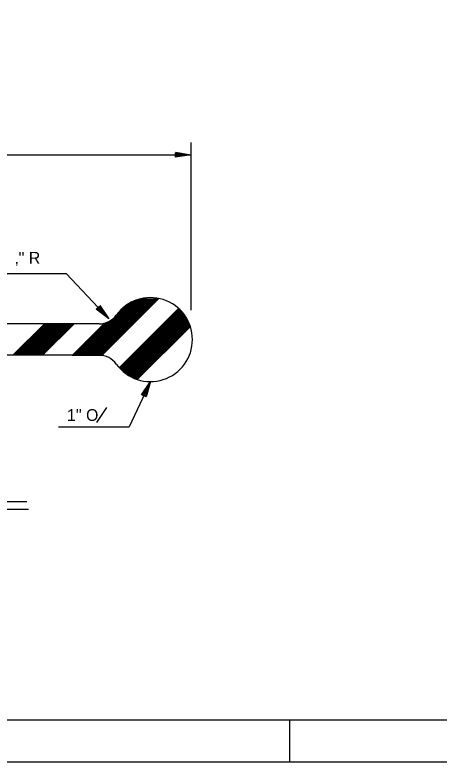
# Model space of a CAD drawing. Extents: x 44743.44 to 44747.1, y 44738.46 to 44741.29.
# Drawn here: x 44744.597 to 44745.018, y 44738.458 to 44739.199 of the extents above; entities that cross this region are included whole.
import ezdxf

# ---------------------------------------------------------------- set-up
doc = ezdxf.new("R2010")
doc.units = 0
for name, color, linetype in [('Level 1', 7, 'Continuous'), ('Level 10', 7, 'Continuous'), ('Level 2', 7, 'Continuous'), ('Level 7', 7, 'Continuous'), ('Level 8', 7, 'Continuous'), ('Level 9', 7, 'Continuous'), ('S-ANNO-TEXT', 7, 'Continuous')]:
    doc.layers.add(name, color=color, linetype=linetype)

msp = doc.modelspace()

# ---------------------------------------------------------------- linework, layer by layer
at = {"layer": 'Level 1'}
for p, q in [((44744.77199, 44738.90593), (44744.77199, 44739.0724)), ((44744.02249, 44739.06029), (44744.77199, 44739.06029)), ((44744.76766, 44739.06029), (44744.76766, 44739.06029)), ((44744.77199, 44739.06029), (44744.77199, 44739.06029)), ((44744.68736, 44738.90061), (44744.68736, 44738.90061)), ((44744.69033, 44738.89745), (44744.69033, 44738.89745)), ((44744.73162, 44738.83523), (44744.73162, 44738.83523)), ((44744.72976, 44738.83132), (44744.72976, 44738.83132))]:
    msp.add_line(p, q, dxfattribs=at)
msp.add_lwpolyline([(44743.43805, 44741.29183), (44747.10474, 44741.29183), (44747.10474, 44738.45783), (44743.43805, 44738.45783)], close=True, dxfattribs=at)
for points in [[(44744.75641, 44739.06287), (44744.77199, 44739.06029), (44744.75641, 44739.0577), (44744.75641, 44739.06212), (44744.76766, 44739.06029), (44744.75708, 44739.05854), (44744.75708, 44739.06137), (44744.76349, 44739.06029), (44744.75774, 44739.05937), (44744.75774, 44739.06054), (44744.75916, 44739.06029)], [(44744.75911, 44738.90712), (44744.75995, 44738.90712)], [(44744.62573, 44738.8922), (44744.65531, 44738.8922)], [(44744.76831, 44738.85763), (44744.76837, 44738.85763)]]:
    msp.add_lwpolyline(points, dxfattribs=at)
at = {"layer": 'Level 10'}
for p, q in [((44744.68086, 44738.89253), (44744.47322, 44738.89253)), ((44744.68086, 44738.86128), (44744.47322, 44738.86128)), ((44744.18607, 44738.71631), (44744.60885, 44738.71631)), ((44744.18494, 44738.7086), (44744.61054, 44738.7086)), ((44744.86974, 44738.45783), (44744.86974, 44738.49983))]:
    msp.add_line(p, q, dxfattribs=at)
for centre, radius, start, end in [((44744.73162, 44738.8769), 0.04167, 215.68525, 144.31912), ((44744.68085, 44738.91336), 0.02083, 270, 324.31466), ((44744.68085, 44738.84044), 0.02083, 35.68534, 90)]:
    msp.add_arc(centre, radius, start, end, dxfattribs=at)
at = {"layer": 'Level 2'}
for p, q in [((44744.58524, 44738.94247), (44744.648, 44738.94247)), ((44744.69033, 44738.89745), (44744.648, 44738.94247)), ((44744.73162, 44738.83523), (44744.71037, 44738.79038)), ((44744.64039, 44738.79038), (44744.71037, 44738.79038))]:
    msp.add_line(p, q, dxfattribs=at)
for points in [[(44744.68154, 44738.91058), (44744.69033, 44738.89745), (44744.67777, 44738.90704), (44744.68099, 44738.91007), (44744.68736, 44738.90061), (44744.67884, 44738.90712), (44744.6809, 44738.90907), (44744.6845, 44738.90365), (44744.6799, 44738.9072), (44744.68074, 44738.90801), (44744.68154, 44738.90681)], [(44744.72261, 44738.82226), (44744.73162, 44738.83523), (44744.72729, 44738.82005), (44744.72329, 44738.82193), (44744.72976, 44738.83132), (44744.72682, 44738.82101), (44744.72425, 44738.82221), (44744.72798, 44738.82756), (44744.72635, 44738.82196), (44744.7253, 44738.82246), (44744.72613, 44738.82364)]]:
    msp.add_lwpolyline(points, dxfattribs=at)
at = {"layer": 'Level 7'}
msp.add_line((44744.67844, 44738.79478), (44744.6882, 44738.80954), dxfattribs=at)
at = {"layer": 'Level 8'}
for points in [[(44744.68345, 44738.86111), (44744.74004, 44738.9177)], [(44744.71705, 44738.91618), (44744.73826, 44738.91618)], [(44744.72182, 44738.91748), (44744.73957, 44738.91748)], [(44744.7041, 44738.90837), (44744.7305, 44738.90837)], [(44744.70584, 44738.90967), (44744.7318, 44738.90967)], [(44744.70759, 44738.91097), (44744.73309, 44738.91097)], [(44744.70957, 44738.91228), (44744.73439, 44738.91228)], [(44744.71156, 44738.91358), (44744.73568, 44738.91358)], [(44744.71409, 44738.91488), (44744.73697, 44738.91488)], [(44744.69848, 44738.90186), (44744.72404, 44738.90186)], [(44744.69942, 44738.90316), (44744.72533, 44738.90316)], [(44744.70036, 44738.90446), (44744.72662, 44738.90446)], [(44744.70073, 44738.84893), (44744.75959, 44738.90779)], [(44744.70154, 44738.90577), (44744.72791, 44738.90577)], [(44744.7027, 44738.90707), (44744.72921, 44738.90707)], [(44744.75387, 44738.90191), (44744.76461, 44738.90191)], [(44744.75518, 44738.90321), (44744.76373, 44738.90321)], [(44744.75649, 44738.90452), (44744.76285, 44738.90452)], [(44744.75781, 44738.90582), (44744.76142, 44738.90582)], [(44744.68858, 44738.89405), (44744.71626, 44738.89405)], [(44744.69134, 44738.89535), (44744.71756, 44738.89535)], [(44744.69333, 44738.89665), (44744.71886, 44738.89665)], [(44744.6948, 44738.89795), (44744.72015, 44738.89795)], [(44744.69615, 44738.89926), (44744.72144, 44738.89926)], [(44744.69736, 44738.90056), (44744.72273, 44738.90056)], [(44744.74601, 44738.8941), (44744.76956, 44738.8941)], [(44744.74732, 44738.8954), (44744.76893, 44738.8954)], [(44744.74863, 44738.8967), (44744.76831, 44738.8967)], [(44744.74994, 44738.89801), (44744.76761, 44738.89801)], [(44744.75125, 44738.89931), (44744.76684, 44738.89931)], [(44744.75256, 44738.90061), (44744.76573, 44738.90061)], [(44744.59522, 44738.86128), (44744.62647, 44738.89253)], [(44744.62059, 44738.887), (44744.65015, 44738.887)], [(44744.62188, 44738.8883), (44744.65144, 44738.8883)], [(44744.62316, 44738.8896), (44744.65272, 44738.8896)], [(44744.62445, 44738.8909), (44744.65401, 44738.8909)], [(44744.62468, 44738.86128), (44744.65593, 44738.89253)], [(44744.65415, 44738.86128), (44744.68606, 44738.89318)], [(44744.67874, 44738.88623), (44744.7085, 44738.88623)], [(44744.68005, 44738.88754), (44744.7098, 44738.88754)], [(44744.68135, 44738.88884), (44744.71109, 44738.88884)], [(44744.68265, 44738.89014), (44744.71239, 44738.89014)], [(44744.68395, 44738.89144), (44744.71368, 44738.89144)], [(44744.68525, 44738.89275), (44744.71497, 44738.89275)], [(44744.71859, 44738.83733), (44744.7712, 44738.88992)], [(44744.73815, 44738.88629), (44744.76704, 44738.88629)], [(44744.73946, 44738.88759), (44744.76833, 44738.88759)], [(44744.74077, 44738.88889), (44744.76961, 44738.88889)], [(44744.74208, 44738.89019), (44744.77051, 44738.89019)], [(44744.74339, 44738.8915), (44744.77036, 44738.8915)], [(44744.7447, 44738.8928), (44744.77019, 44738.8928)], [(44744.61286, 44738.87918), (44744.64242, 44738.87918)], [(44744.61415, 44738.88048), (44744.64371, 44738.88048)], [(44744.61544, 44738.88179), (44744.64499, 44738.88179)], [(44744.61672, 44738.88309), (44744.64629, 44738.88309)], [(44744.61801, 44738.88439), (44744.64758, 44738.88439)], [(44744.61931, 44738.88569), (44744.64886, 44738.88569)], [(44744.67093, 44738.87842), (44744.70073, 44738.87842)], [(44744.67223, 44738.87972), (44744.70204, 44738.87972)], [(44744.67354, 44738.88103), (44744.70333, 44738.88103)], [(44744.67484, 44738.88233), (44744.70462, 44738.88233)], [(44744.67614, 44738.88363), (44744.70591, 44738.88363)], [(44744.67744, 44738.88493), (44744.70721, 44738.88493)], [(44744.73031, 44738.87847), (44744.7593, 44738.87847)], [(44744.73161, 44738.87978), (44744.76059, 44738.87978)], [(44744.73292, 44738.88108), (44744.76188, 44738.88108)], [(44744.73423, 44738.88238), (44744.76316, 44738.88238)], [(44744.73555, 44738.88368), (44744.76445, 44738.88368)], [(44744.73684, 44738.88498), (44744.76574, 44738.88498)], [(44744.60514, 44738.87137), (44744.63469, 44738.87137)], [(44744.60642, 44738.87267), (44744.63598, 44738.87267)], [(44744.60771, 44738.87397), (44744.63726, 44738.87397)], [(44744.609, 44738.87528), (44744.63856, 44738.87528)], [(44744.61029, 44738.87658), (44744.63985, 44738.87658)], [(44744.61158, 44738.87788), (44744.64113, 44738.87788)], [(44744.66442, 44738.87191), (44744.69427, 44738.87191)], [(44744.66572, 44738.87321), (44744.69557, 44738.87321)], [(44744.66702, 44738.87452), (44744.69686, 44738.87452)], [(44744.66833, 44738.87582), (44744.69815, 44738.87582)], [(44744.66963, 44738.87712), (44744.69944, 44738.87712)], [(44744.72375, 44738.87196), (44744.75285, 44738.87196)], [(44744.72507, 44738.87327), (44744.75414, 44738.87327)], [(44744.72637, 44738.87457), (44744.75543, 44738.87457)], [(44744.72768, 44738.87587), (44744.75672, 44738.87587)], [(44744.72899, 44738.87717), (44744.758, 44738.87717)], [(44744.5987, 44738.86486), (44744.62825, 44738.86486)], [(44744.59998, 44738.86616), (44744.62954, 44738.86616)], [(44744.60127, 44738.86746), (44744.63083, 44738.86746)], [(44744.60257, 44738.86877), (44744.63212, 44738.86877)], [(44744.60385, 44738.87007), (44744.6334, 44738.87007)], [(44744.65661, 44738.8641), (44744.68651, 44738.8641)], [(44744.65791, 44738.8654), (44744.68781, 44738.8654)], [(44744.65921, 44738.8667), (44744.6891, 44738.8667)], [(44744.66051, 44738.86801), (44744.69039, 44738.86801)], [(44744.66182, 44738.86931), (44744.69169, 44738.86931)], [(44744.66312, 44738.87061), (44744.69298, 44738.87061)], [(44744.71589, 44738.86415), (44744.74511, 44738.86415)], [(44744.7172, 44738.86545), (44744.7464, 44738.86545)], [(44744.71851, 44738.86676), (44744.74769, 44738.86676)], [(44744.71983, 44738.86806), (44744.74898, 44738.86806)], [(44744.72113, 44738.86936), (44744.75027, 44738.86936)], [(44744.72244, 44738.87066), (44744.75156, 44738.87066)], [(44744.59612, 44738.86226), (44744.62567, 44738.86226)], [(44744.59741, 44738.86356), (44744.62696, 44738.86356)], [(44744.654, 44738.8615), (44744.68392, 44738.8615)], [(44744.65531, 44738.8628), (44744.68522, 44738.8628)], [(44744.70804, 44738.85634), (44744.73738, 44738.85634)], [(44744.70934, 44738.85764), (44744.73867, 44738.85764)], [(44744.71065, 44738.85894), (44744.73995, 44738.85894)], [(44744.71196, 44738.86025), (44744.74124, 44738.86025)], [(44744.71327, 44738.86155), (44744.74254, 44738.86155)], [(44744.71459, 44738.86285), (44744.74383, 44738.86285)], [(44744.70148, 44738.84983), (44744.73094, 44738.84983)], [(44744.7028, 44738.85113), (44744.73223, 44738.85113)], [(44744.7041, 44738.85243), (44744.73351, 44738.85243)], [(44744.70541, 44738.85373), (44744.73481, 44738.85373)], [(44744.70672, 44738.85504), (44744.73609, 44738.85504)], [(44744.70133, 44738.84853), (44744.72965, 44738.84853)], [(44744.70285, 44738.84722), (44744.72836, 44738.84722)], [(44744.70418, 44738.84592), (44744.72707, 44738.84592)], [(44744.70548, 44738.84462), (44744.72579, 44738.84462)], [(44744.70717, 44738.84332), (44744.72449, 44738.84332)], [(44744.7089, 44738.84202), (44744.7232, 44738.84202)], [(44744.71164, 44738.84071), (44744.72191, 44738.84071)], [(44744.71439, 44738.83941), (44744.72063, 44738.83941)], [(44744.71699, 44738.83811), (44744.71934, 44738.83811)]]:
    msp.add_lwpolyline(points, dxfattribs=at)
at = {"layer": 'Level 9'}
msp.add_line((44743.56305, 44738.49983), (44746.83374, 44738.49983), dxfattribs=at)

# ---------------------------------------------------------------- texts
at = {"layer": 'S-ANNO-TEXT'}
for s, p in [("‚'' R", (44744.59725, 44738.95223)), ("1'' O", (44744.64881, 44738.79623))]:
    msp.add_text(s, height=0.011667, dxfattribs=at).set_placement(p)

doc.saveas('drawing.dxf')
